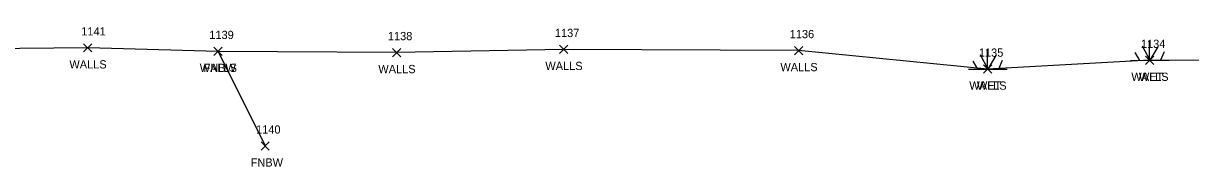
# Model space of a CAD drawing. Extents: x 1519347 to 1522636, y 378779 to 379832.
# Drawn here: x 1521601.3 to 1521885.3, y 378876 to 378910.7 of the extents above; entities that cross this region are included whole.
import ezdxf

# ---------------------------------------------------------------- set-up
doc = ezdxf.new("R2010")
doc.units = 0
for name, color, linetype in [('L_A', 7, 'Continuous'), ('L_I', 7, 'Continuous'), ('L_TIC', 7, 'Continuous'), ('LFNC', 7, 'Continuous'), ('LWET', 7, 'Continuous'), ('LWS', 7, 'Continuous')]:
    doc.layers.add(name, color=color, linetype=linetype)

msp = doc.modelspace()

# ---------------------------------------------------------------- linework, layer by layer
at = {"layer": 'L_TIC'}
for points in [[(1521615.94, 378903.79), (1521617.94, 378905.79)], [(1521617.94, 378903.79), (1521615.94, 378905.79)], [(1521647.67, 378902.93), (1521649.67, 378904.93)], [(1521649.67, 378902.93), (1521647.67, 378904.93)], [(1521647.67, 378902.93), (1521649.67, 378904.93)], [(1521649.67, 378902.93), (1521647.67, 378904.93)], [(1521691.11, 378902.65), (1521693.11, 378904.65)], [(1521693.11, 378902.65), (1521691.11, 378904.65)], [(1521731.75, 378903.41), (1521733.75, 378905.41)], [(1521733.75, 378903.41), (1521731.75, 378905.41)], [(1521788.94, 378903.13), (1521790.94, 378905.13)], [(1521790.94, 378903.13), (1521788.94, 378905.13)], [(1521874.34, 378900.77), (1521876.34, 378902.77)], [(1521876.34, 378900.77), (1521874.34, 378902.77)], [(1521834.92, 378898.64), (1521836.92, 378900.64)], [(1521836.92, 378898.64), (1521834.92, 378900.64)], [(1521659.13, 378879.99), (1521661.13, 378881.99)], [(1521661.13, 378879.99), (1521659.13, 378881.99)]]:
    msp.add_lwpolyline(points, dxfattribs=at)
at = {"layer": 'LFNC'}
msp.add_lwpolyline([(1521648.67, 378903.93), (1521660.13, 378880.99)], dxfattribs=at)
at = {"layer": 'LWET'}
for p, q in [((1521873.55, 378905.32), (1521875.37, 378901.8)), ((1521875.34, 378901.77), (1521875.32, 378906.51)), ((1521877.36, 378905.05), (1521875.37, 378901.8)), ((1521834.13, 378903.19), (1521835.95, 378899.66)), ((1521835.92, 378899.64), (1521835.89, 378904.38)), ((1521837.93, 378902.92), (1521835.95, 378899.66)), ((1521870.69, 378901.74), (1521880.06, 378901.8)), ((1521871.73, 378903.67), (1521872.89, 378901.74)), ((1521875.49, 378901.95), (1521875.37, 378901.95)), ((1521878.85, 378903.84), (1521877.96, 378901.8)), ((1521831.26, 378899.61), (1521840.64, 378899.66)), ((1521832.31, 378901.54), (1521833.47, 378899.61)), ((1521836.07, 378899.82), (1521835.95, 378899.82)), ((1521839.42, 378901.7), (1521838.54, 378899.66))]:
    msp.add_line(p, q, dxfattribs=at)
msp.add_lwpolyline([(1521875.34, 378901.77), (1521835.92, 378899.64)], dxfattribs=at)
at = {"layer": 'LWS'}
msp.add_lwpolyline([(1522445.31, 378910.72), (1522401.54, 378910.43), (1522348.21, 378909.74), (1522295.88, 378908.39), (1522245.08, 378908.42), (1522202.2, 378906.68), (1522157.16, 378906.96), (1522120.07, 378904.84), (1522091.12, 378905.13), (1522034.79, 378905.64), (1521976.72, 378902.28), (1521929.9, 378901.52), (1521875.34, 378901.77), (1521835.92, 378899.64), (1521789.94, 378904.13), (1521732.75, 378904.41), (1521692.11, 378903.65), (1521648.67, 378903.93), (1521616.94, 378904.79), (1521567.34, 378904.32)], dxfattribs=at)

# ---------------------------------------------------------------- texts
at = {"layer": 'L_A'}
for s, p in [('WALLS', (1521612.49, 378899.79)), ('WALLS', (1521644.21, 378898.93)), ('FNBW', (1521645.14, 378898.93)), ('WALLS', (1521687.66, 378898.65)), ('WALLS', (1521728.3, 378899.41)), ('WALLS', (1521785.49, 378899.13)), ('WALLS', (1521831.46, 378894.64)), ('WET', (1521833.3, 378894.64)), ('WALLS', (1521870.89, 378896.77)), ('WET', (1521872.72, 378896.77)), ('FNBW', (1521656.6, 378875.99))]:
    msp.add_text(s, height=2, dxfattribs=at).set_placement(p)
at = {"layer": 'L_I'}
for s, p in [('1141', (1521615.39, 378907.79)), ('1139', (1521646.54, 378906.93)), ('1139', (1521646.54, 378906.93)), ('1138', (1521689.99, 378906.65)), ('1137', (1521730.63, 378907.41)), ('1136', (1521787.76, 378907.13)), ('1135', (1521833.79, 378902.64)), ('1135', (1521833.79, 378902.64)), ('1134', (1521873.22, 378904.77)), ('1134', (1521873.22, 378904.77)), ('1140', (1521657.92, 378883.99))]:
    msp.add_text(s, height=2, dxfattribs=at).set_placement(p)

doc.saveas('drawing.dxf')
